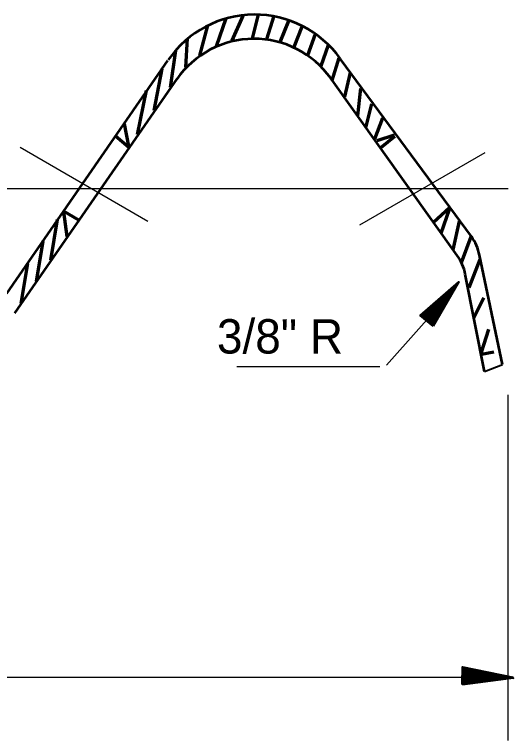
# Model space of a CAD drawing. Extents: x 895.6 to 930.4, y -2278.6 to -2254.7.
# Drawn here: x 905.969 to 907.838, y -2274.88 to -2272.162 of the extents above; entities that cross this region are included whole.
import ezdxf

# ---------------------------------------------------------------- set-up
doc = ezdxf.new("R2010")
doc.units = 0
doc.header["$LTSCALE"] = 0.051
doc.layers.add('1', color=7, linetype='Continuous', lineweight=70)
doc.layers.add('3', color=7, linetype='Continuous', lineweight=40)

msp = doc.modelspace()

# ---------------------------------------------------------------- hatches: boundary and pattern name
at = {"layer": '3'}
for points in [[(907.537, -2273.32908), (907.48792, -2273.28942), (907.63267, -2273.1625), (907.63267, -2273.1625)], [(907.5345, -2273.32642), (907.49108, -2273.29), (907.62125, -2273.1765), (907.62125, -2273.1765)], [(907.53342, -2273.324), (907.49342, -2273.29175), (907.61083, -2273.18925), (907.61083, -2273.18925)], [(907.5315, -2273.32167), (907.4955, -2273.29267), (907.6015, -2273.20067), (907.6015, -2273.20067)], [(907.53, -2273.32017), (907.498, -2273.29375), (907.59325, -2273.21058), (907.59325, -2273.21058)], [(907.52925, -2273.318), (907.50008, -2273.29433), (907.58583, -2273.21967), (907.58583, -2273.21967)], [(907.52775, -2273.31675), (907.50158, -2273.29567), (907.57867, -2273.22775), (907.57867, -2273.22775)], [(907.52667, -2273.31508), (907.50358, -2273.29567), (907.57258, -2273.23567), (907.57258, -2273.23567)], [(907.52592, -2273.31433), (907.505, -2273.29675), (907.56733, -2273.242), (907.56733, -2273.242)], [(907.52525, -2273.31267), (907.50608, -2273.2975), (907.56233, -2273.24817), (907.56233, -2273.24817)], [(907.52433, -2273.31175), (907.50742, -2273.29767), (907.55758, -2273.25367), (907.55758, -2273.25367)], [(907.52375, -2273.31092), (907.50858, -2273.29775), (907.55383, -2273.25858), (907.55383, -2273.25858)], [(907.523, -2273.31), (907.50925, -2273.29883), (907.55025, -2273.263), (907.55025, -2273.263)], [(907.52242, -2273.30933), (907.50992, -2273.29933), (907.54708, -2273.267), (907.54708, -2273.267)], [(907.522, -2273.30858), (907.51083, -2273.29958), (907.54367, -2273.27042), (907.54367, -2273.27042)], [(907.52192, -2273.30758), (907.51142, -2273.29975), (907.54117, -2273.27342), (907.54117, -2273.27342)], [(907.52158, -2273.30717), (907.51208, -2273.29958), (907.53917, -2273.27658), (907.53917, -2273.27658)], [(907.52108, -2273.30692), (907.51267, -2273.29975), (907.53683, -2273.27875), (907.53683, -2273.27875)], [(907.52067, -2273.30617), (907.51342, -2273.30008), (907.53525, -2273.2815), (907.53525, -2273.2815)], [(907.52042, -2273.30583), (907.51417, -2273.30083), (907.53325, -2273.28375), (907.53325, -2273.28375)], [(907.52017, -2273.30567), (907.51483, -2273.30142), (907.53225, -2273.28558), (907.53225, -2273.28558)], [(907.51983, -2273.30558), (907.51508, -2273.3015), (907.53058, -2273.287), (907.53058, -2273.287)], [(907.51975, -2273.30533), (907.51533, -2273.30158), (907.52925, -2273.28842), (907.52925, -2273.28842)], [(907.51967, -2273.30517), (907.51575, -2273.30167), (907.52842, -2273.29), (907.52842, -2273.29)], [(907.645, -2274.66758), (907.64708, -2274.60433), (907.83558, -2274.64242), (907.83558, -2274.64242)], [(907.64717, -2274.67225), (907.64925, -2274.609), (907.83775, -2274.64708), (907.83775, -2274.64708)], [(907.64817, -2274.669), (907.65, -2274.61225), (907.81958, -2274.64642), (907.81958, -2274.64642)], [(907.649, -2274.66625), (907.65067, -2274.61508), (907.80333, -2274.64592), (907.80333, -2274.64592)], [(907.64983, -2274.66367), (907.65133, -2274.61775), (907.78867, -2274.64542), (907.78867, -2274.64542)], [(907.65042, -2274.66158), (907.65192, -2274.62017), (907.7755, -2274.645), (907.7755, -2274.645)], [(907.65125, -2274.65942), (907.65242, -2274.62217), (907.76367, -2274.64467), (907.76367, -2274.64467)], [(907.65167, -2274.65758), (907.65275, -2274.62392), (907.753, -2274.64417), (907.753, -2274.64417)], [(907.65225, -2274.656), (907.65317, -2274.62575), (907.74325, -2274.644), (907.74325, -2274.644)], [(907.65258, -2274.6545), (907.65358, -2274.62717), (907.73467, -2274.6435), (907.73467, -2274.6435)], [(907.65308, -2274.65308), (907.654, -2274.6285), (907.72692, -2274.64342), (907.72692, -2274.64342)], [(907.6535, -2274.65183), (907.65425, -2274.62992), (907.71983, -2274.64308), (907.71983, -2274.64308)], [(907.65375, -2274.65075), (907.6545, -2274.631), (907.71358, -2274.64275), (907.71358, -2274.64275)], [(907.65417, -2274.64983), (907.65467, -2274.63192), (907.70775, -2274.64267), (907.70775, -2274.64267)], [(907.6545, -2274.64883), (907.65492, -2274.63283), (907.70283, -2274.64258), (907.70283, -2274.64258)], [(907.65467, -2274.64808), (907.65517, -2274.63367), (907.69817, -2274.64242), (907.69817, -2274.64242)], [(907.65492, -2274.64742), (907.65525, -2274.63433), (907.69408, -2274.64208), (907.69408, -2274.64208)], [(907.65508, -2274.64675), (907.6555, -2274.63492), (907.69033, -2274.642), (907.69033, -2274.642)], [(907.65525, -2274.64608), (907.65558, -2274.63558), (907.68708, -2274.64192), (907.68708, -2274.64192)], [(907.6555, -2274.64575), (907.65575, -2274.63617), (907.68408, -2274.64192), (907.68408, -2274.64192)], [(907.65567, -2274.64533), (907.65592, -2274.63667), (907.68142, -2274.64192), (907.68142, -2274.64192)], [(907.65583, -2274.645), (907.65608, -2274.63733), (907.679, -2274.642), (907.679, -2274.642)], [(907.65583, -2274.64458), (907.65608, -2274.63767), (907.67683, -2274.64192), (907.67683, -2274.64192)], [(907.656, -2274.64417), (907.65625, -2274.638), (907.67483, -2274.64167), (907.67483, -2274.64167)], [(907.65608, -2274.644), (907.65633, -2274.63842), (907.67308, -2274.64175), (907.67308, -2274.64175)]]:
    msp.add_hatch(color=256, dxfattribs=at).paths.add_polyline_path(points)

# ---------------------------------------------------------------- linework, layer by layer
at = {"layer": '1'}
for p, q in [((906.72533, -2272.28), (906.76175, -2272.176)), ((906.7845, -2272.2595), (906.82492, -2272.16675)), ((906.85992, -2272.25142), (906.88333, -2272.16208)), ((906.91458, -2272.25492), (906.94208, -2272.16675)), ((906.66383, -2272.31542), (906.69375, -2272.20367)), ((906.96358, -2272.26517), (906.99692, -2272.18517)), ((907.016, -2272.28342), (907.04658, -2272.20675)), ((907.06733, -2272.31417), (907.09583, -2272.23475)), ((906.61025, -2272.35975), (906.61725, -2272.252)), ((907.1175, -2272.35417), (907.14508, -2272.27508)), ((906.55325, -2272.43517), (906.57375, -2272.29642)), ((907.1585, -2272.40892), (907.18533, -2272.32425)), ((906.49275, -2272.52175), (906.52175, -2272.36517)), ((907.20642, -2272.47058), (907.22683, -2272.379)), ((906.43, -2272.61075), (906.464, -2272.44692)), ((907.25542, -2272.54), (907.2665, -2272.43767)), ((907.28492, -2272.58692), (907.30775, -2272.49658)), ((907.31808, -2272.628), (907.34808, -2272.5495)), ((906.39692, -2272.65517), (906.381, -2272.57092)), ((907.39108, -2272.61317), (907.326, -2272.63475)), ((906.39692, -2272.65992), (906.34733, -2272.617)), ((907.34092, -2272.65992), (907.39342, -2272.617)), ((907.53783, -2272.94), (907.59792, -2272.88508)), ((906.21008, -2272.93142), (906.15292, -2272.89825)), ((906.16608, -2272.99317), (906.15408, -2272.90075)), ((907.5675, -2272.98117), (907.59792, -2272.89025)), ((906.10575, -2273.08175), (906.13083, -2272.93)), ((907.6125, -2273.04275), (907.63608, -2272.93575)), ((907.64283, -2273.09067), (907.6795, -2272.993)), ((906.05125, -2273.1615), (906.07633, -2273.01025)), ((905.9945, -2273.24425), (906.01933, -2273.094)), ((907.67133, -2273.18417), (907.71283, -2273.07858)), ((907.68942, -2273.296), (907.72708, -2273.22275)), ((907.71808, -2273.42592), (907.7455, -2273.33992)), ((907.76375, -2273.42592), (907.71808, -2273.43517))]:
    msp.add_line(p, q, dxfattribs=at)
at = {"layer": '1', "lineweight": 53}
for p, q in [((906.5425, -2272.33442), (905.93942, -2273.20625)), ((907.6805, -2272.99367), (907.18992, -2272.32958)), ((906.57725, -2272.40325), (905.9695, -2273.28075)), ((907.62742, -2273.06475), (907.15283, -2272.39967)), ((907.79658, -2273.47292), (907.7105, -2273.06342)), ((907.72892, -2273.498), (907.65742, -2273.13442))]:
    msp.add_line(p, q, dxfattribs=at)
at = {"layer": '1', "lineweight": 25}
for p, q in [((906.46875, -2272.9365), (905.9905, -2272.6605)), ((907.26292, -2272.94975), (907.73225, -2272.67892)), ((900.56375, -2272.81325), (907.81792, -2272.81325)), ((907.36208, -2273.47483), (907.59458, -2273.21383)), ((906.80125, -2273.47925), (907.33717, -2273.47925)), ((907.81792, -2274.88), (907.81792, -2273.58558)), ((900.23575, -2274.64308), (907.81792, -2274.64308))]:
    msp.add_line(p, q, dxfattribs=at)
at = {"layer": '1', "lineweight": 40}
msp.add_line((907.72892, -2273.498), (907.79658, -2273.47292), dxfattribs=at)
at = {"layer": '1', "lineweight": 53}
for centre, radius, start, end in [((906.86874, -2272.5564), 0.39401, 35.4894, 145.25957), ((906.86658, -2272.60524), 0.3523, 35.49221, 145.25957), ((907.53128, -2273.0989), 0.18263, 11.22124, 35.17721), ((907.47815, -2273.16989), 0.18263, 11.22124, 35.17721)]:
    msp.add_arc(centre, radius, start, end, dxfattribs=at)
at = {"layer": '3'}
for points in [[(907.537, -2273.32908), (907.48792, -2273.28942), (907.63267, -2273.1625), (907.63267, -2273.1625)], [(907.5345, -2273.32642), (907.49108, -2273.29), (907.62125, -2273.1765), (907.62125, -2273.1765)], [(907.53342, -2273.324), (907.49342, -2273.29175), (907.61083, -2273.18925), (907.61083, -2273.18925)], [(907.5315, -2273.32167), (907.4955, -2273.29267), (907.6015, -2273.20067), (907.6015, -2273.20067)], [(907.53, -2273.32017), (907.498, -2273.29375), (907.59325, -2273.21058), (907.59325, -2273.21058)], [(907.52925, -2273.318), (907.50008, -2273.29433), (907.58583, -2273.21967), (907.58583, -2273.21967)], [(907.52775, -2273.31675), (907.50158, -2273.29567), (907.57867, -2273.22775), (907.57867, -2273.22775)], [(907.52667, -2273.31508), (907.50358, -2273.29567), (907.57258, -2273.23567), (907.57258, -2273.23567)], [(907.52592, -2273.31433), (907.505, -2273.29675), (907.56733, -2273.242), (907.56733, -2273.242)], [(907.52525, -2273.31267), (907.50608, -2273.2975), (907.56233, -2273.24817), (907.56233, -2273.24817)], [(907.52433, -2273.31175), (907.50742, -2273.29767), (907.55758, -2273.25367), (907.55758, -2273.25367)], [(907.52375, -2273.31092), (907.50858, -2273.29775), (907.55383, -2273.25858), (907.55383, -2273.25858)], [(907.523, -2273.31), (907.50925, -2273.29883), (907.55025, -2273.263), (907.55025, -2273.263)], [(907.52242, -2273.30933), (907.50992, -2273.29933), (907.54708, -2273.267), (907.54708, -2273.267)], [(907.522, -2273.30858), (907.51083, -2273.29958), (907.54367, -2273.27042), (907.54367, -2273.27042)], [(907.52192, -2273.30758), (907.51142, -2273.29975), (907.54117, -2273.27342), (907.54117, -2273.27342)], [(907.52158, -2273.30717), (907.51208, -2273.29958), (907.53917, -2273.27658), (907.53917, -2273.27658)], [(907.52108, -2273.30692), (907.51267, -2273.29975), (907.53683, -2273.27875), (907.53683, -2273.27875)], [(907.52067, -2273.30617), (907.51342, -2273.30008), (907.53525, -2273.2815), (907.53525, -2273.2815)], [(907.52042, -2273.30583), (907.51417, -2273.30083), (907.53325, -2273.28375), (907.53325, -2273.28375)], [(907.52017, -2273.30567), (907.51483, -2273.30142), (907.53225, -2273.28558), (907.53225, -2273.28558)], [(907.51983, -2273.30558), (907.51508, -2273.3015), (907.53058, -2273.287), (907.53058, -2273.287)], [(907.51975, -2273.30533), (907.51533, -2273.30158), (907.52925, -2273.28842), (907.52925, -2273.28842)], [(907.51967, -2273.30517), (907.51575, -2273.30167), (907.52842, -2273.29), (907.52842, -2273.29)], [(907.645, -2274.66758), (907.64708, -2274.60433), (907.83558, -2274.64242), (907.83558, -2274.64242)], [(907.64717, -2274.67225), (907.64925, -2274.609), (907.83775, -2274.64708), (907.83775, -2274.64708)], [(907.64817, -2274.669), (907.65, -2274.61225), (907.81958, -2274.64642), (907.81958, -2274.64642)], [(907.649, -2274.66625), (907.65067, -2274.61508), (907.80333, -2274.64592), (907.80333, -2274.64592)], [(907.64983, -2274.66367), (907.65133, -2274.61775), (907.78867, -2274.64542), (907.78867, -2274.64542)], [(907.65042, -2274.66158), (907.65192, -2274.62017), (907.7755, -2274.645), (907.7755, -2274.645)], [(907.65125, -2274.65942), (907.65242, -2274.62217), (907.76367, -2274.64467), (907.76367, -2274.64467)], [(907.65167, -2274.65758), (907.65275, -2274.62392), (907.753, -2274.64417), (907.753, -2274.64417)], [(907.65225, -2274.656), (907.65317, -2274.62575), (907.74325, -2274.644), (907.74325, -2274.644)], [(907.65258, -2274.6545), (907.65358, -2274.62717), (907.73467, -2274.6435), (907.73467, -2274.6435)], [(907.65308, -2274.65308), (907.654, -2274.6285), (907.72692, -2274.64342), (907.72692, -2274.64342)], [(907.6535, -2274.65183), (907.65425, -2274.62992), (907.71983, -2274.64308), (907.71983, -2274.64308)], [(907.65375, -2274.65075), (907.6545, -2274.631), (907.71358, -2274.64275), (907.71358, -2274.64275)], [(907.65417, -2274.64983), (907.65467, -2274.63192), (907.70775, -2274.64267), (907.70775, -2274.64267)], [(907.6545, -2274.64883), (907.65492, -2274.63283), (907.70283, -2274.64258), (907.70283, -2274.64258)], [(907.65467, -2274.64808), (907.65517, -2274.63367), (907.69817, -2274.64242), (907.69817, -2274.64242)], [(907.65492, -2274.64742), (907.65525, -2274.63433), (907.69408, -2274.64208), (907.69408, -2274.64208)], [(907.65508, -2274.64675), (907.6555, -2274.63492), (907.69033, -2274.642), (907.69033, -2274.642)], [(907.65525, -2274.64608), (907.65558, -2274.63558), (907.68708, -2274.64192), (907.68708, -2274.64192)], [(907.6555, -2274.64575), (907.65575, -2274.63617), (907.68408, -2274.64192), (907.68408, -2274.64192)], [(907.65567, -2274.64533), (907.65592, -2274.63667), (907.68142, -2274.64192), (907.68142, -2274.64192)], [(907.65583, -2274.645), (907.65608, -2274.63733), (907.679, -2274.642), (907.679, -2274.642)], [(907.65583, -2274.64458), (907.65608, -2274.63767), (907.67683, -2274.64192), (907.67683, -2274.64192)], [(907.656, -2274.64417), (907.65625, -2274.638), (907.67483, -2274.64167), (907.67483, -2274.64167)], [(907.65608, -2274.644), (907.65633, -2274.63842), (907.67308, -2274.64175), (907.67308, -2274.64175)]]:
    msp.add_lwpolyline(points, close=True, dxfattribs=at)

# ---------------------------------------------------------------- texts
at = {"layer": '1'}
msp.add_text('3/8" R', height=0.1286, dxfattribs=at).set_placement((906.72733, -2273.43125))

doc.saveas('drawing.dxf')
